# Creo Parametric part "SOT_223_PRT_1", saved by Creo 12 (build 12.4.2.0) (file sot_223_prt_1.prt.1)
Units: Custom; MM, KILOGRAM, SECS

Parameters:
  PTC_WM_ITERATION = "0"
  PTC_WM_VERSION = "-.0"
  PTC_WM_LIFECYCLE_STATE = "In Work"
  PTC_WM_LIFECYCLE = "MO_CADDocument"
  PTC_WM_CREATED_BY = "Maximilian Roepper (Z0017RMS: MO)"
  PTC_WM_CREATED_ON = "18-Sep-26 11:36:42 AM"
  PTC_WM_MODIFIED_BY = "Maximilian Roepper (Z0017RMS: MO)"
  PTC_WM_MODIFIED_ON = "18-Sep-26 11:36:46 AM"
  PDMLINKNUMBER = "PDM000071455273"
  PTC_WM_NAME = "sot_223_prt_1.prt"
  PTC_WM_NUMBER = "PDM000071455273"

Other parameters: WEIGHT, WEIGHT_FACTOR, WEIGHT_ADD, _MASS_TEMP, _DIFF_TEMP, MC_ERRORS, SUPPLIER

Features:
  1. coordinate system
  2. datum plane "PRT_YZ"
  3. datum plane "PRT_XY"
  4. datum plane "PRT_XZ"
  5. coordinate system
  6. datum axis
  7. datum axis
  8. datum axis
  9. coordinate system
  10. imported feature
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
Other named items: PRT, SIEMENS_MO, DRW_VIEW_ORG, PRT_X, PRT_Y, PRT_Z, CS0, ROUGH_GROB

Layers: 00_STD_CSYS-KSYS, 01_STD_PLANES-EBENEN, 02_STD_AXES-ACHSEN, 03_STD_CSYS-KSYS, 24_IMPORT_FEAT-IMPORT_KE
